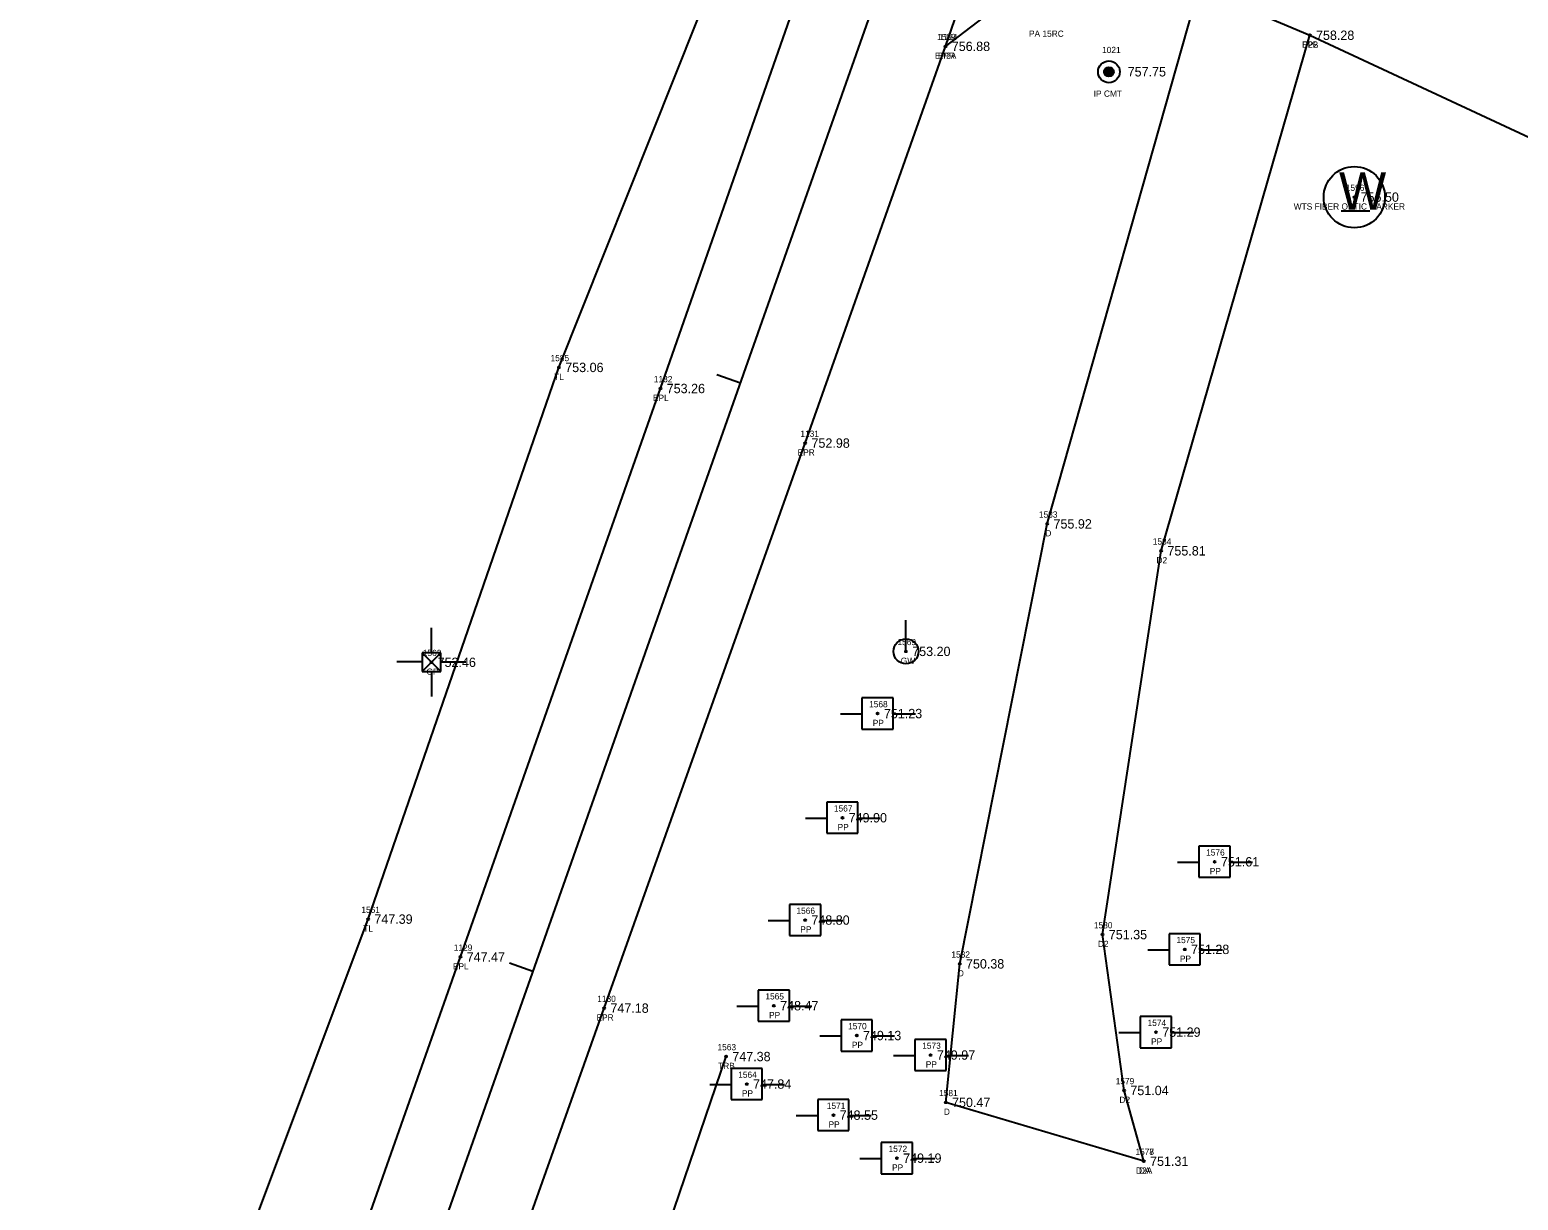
# Model space of a CAD drawing. Extents: x 1736563 to 1738032, y 1150548 to 1154248.
# Drawn here: x 1737559.1 to 1737797.6, y 1153273.7 to 1153461.3 of the extents above; entities that cross this region are included whole.
import ezdxf

# ---------------------------------------------------------------- set-up
doc = ezdxf.new("R2010")
doc.units = 0
for name, color, linetype in [('RD_EX_DR_Pipe_txCode', 7, 'Continuous'), ('RD_EX_Driveway', 7, 'Continuous'), ('RD_EX_Driveway_txCode', 7, 'Continuous'), ('RD_EX_DV_Prop_txCode', 7, 'Continuous'), ('RD_EX_DV_PropPin', 7, 'Continuous'), ('RD_EX_Road', 7, 'Continuous'), ('RD_EX_Road_txCode', 7, 'Continuous'), ('RD_EX_TX_Driveway_ELEV', 7, 'Continuous'), ('RD_EX_TX_DV_Prop_ELEV', 7, 'Continuous'), ('RD_EX_TX_Road_ELEV', 7, 'Continuous'), ('RD_EX_TX_UT_ELEV', 7, 'Continuous'), ('RD_EX_TX_VEG_ELEV', 7, 'Continuous'), ('RD_EX_UT', 7, 'Continuous'), ('RD_EX_UT_txCode', 7, 'Continuous'), ('RD_EX_VEG', 7, 'Continuous'), ('RD_EX_VEG_txCode', 7, 'Continuous'), ('RD_HC_Cl', 7, 'Continuous'), ('RD_HC_Data_Tic', 7, 'Continuous'), ('RD_HC_Survey_ELEV', 7, 'Continuous'), ('RD_SMD_Locator', 7, 'Continuous')]:
    doc.layers.add(name, color=color, linetype=linetype)

msp = doc.modelspace()

# ---------------------------------------------------------------- linework, layer by layer
at = {"layer": 'RD_EX_Driveway'}
for points in [[(1737737.65, 1153279.93), (1737705.92, 1153289.36), (1737708.15, 1153311.57), (1737722.18, 1153382.1), (1737746.44, 1153467.95)], [(1737737.65, 1153279.93), (1737734.49, 1153291.27), (1737731.04, 1153316.26), (1737740.43, 1153377.78), (1737764.24, 1153460.43)]]:
    msp.add_lwpolyline(points, dxfattribs=at)
at = {"layer": 'RD_EX_DV_PropPin'}
for p, q in [((1737731.32, 1153454.38), (1737731.32, 1153454.77)), ((1737731.36, 1153454.28), (1737731.36, 1153454.87)), ((1737731.4, 1153454.2), (1737731.4, 1153454.94)), ((1737731.43, 1153454.15), (1737731.43, 1153455)), ((1737731.47, 1153454.1), (1737731.47, 1153455.05)), ((1737731.5, 1153454.06), (1737731.5, 1153455.09)), ((1737731.54, 1153454.02), (1737731.54, 1153455.12)), ((1737731.57, 1153453.99), (1737731.57, 1153455.16)), ((1737731.61, 1153453.96), (1737731.61, 1153455.18)), ((1737731.64, 1153453.94), (1737731.64, 1153455.21)), ((1737731.68, 1153453.92), (1737731.68, 1153455.23)), ((1737731.71, 1153453.9), (1737731.71, 1153455.25)), ((1737731.75, 1153453.88), (1737731.75, 1153455.27)), ((1737731.78, 1153453.87), (1737731.78, 1153455.28)), ((1737731.82, 1153453.85), (1737731.82, 1153455.29)), ((1737731.85, 1153453.84), (1737731.85, 1153455.3)), ((1737731.89, 1153453.83), (1737731.89, 1153455.31)), ((1737731.92, 1153453.83), (1737731.92, 1153455.32)), ((1737731.96, 1153453.82), (1737731.96, 1153455.33)), ((1737731.99, 1153453.82), (1737731.99, 1153455.33)), ((1737732.03, 1153453.81), (1737732.03, 1153455.33)), ((1737732.06, 1153453.81), (1737732.06, 1153455.33)), ((1737732.1, 1153453.81), (1737732.1, 1153455.33)), ((1737732.13, 1153453.82), (1737732.13, 1153455.33)), ((1737732.17, 1153453.82), (1737732.17, 1153455.33)), ((1737732.2, 1153453.83), (1737732.2, 1153455.32)), ((1737732.24, 1153453.83), (1737732.24, 1153455.31)), ((1737732.27, 1153453.84), (1737732.27, 1153455.3)), ((1737732.31, 1153453.85), (1737732.31, 1153455.29)), ((1737732.34, 1153453.87), (1737732.34, 1153455.28)), ((1737732.38, 1153453.88), (1737732.38, 1153455.27)), ((1737732.41, 1153453.9), (1737732.41, 1153455.25)), ((1737732.45, 1153453.92), (1737732.45, 1153455.23)), ((1737732.48, 1153453.94), (1737732.48, 1153455.21)), ((1737732.52, 1153453.96), (1737732.52, 1153455.18)), ((1737732.55, 1153453.99), (1737732.55, 1153455.16)), ((1737732.59, 1153454.02), (1737732.59, 1153455.12)), ((1737732.62, 1153454.06), (1737732.62, 1153455.09)), ((1737732.66, 1153454.1), (1737732.66, 1153455.05)), ((1737732.69, 1153454.15), (1737732.69, 1153455)), ((1737732.73, 1153454.2), (1737732.73, 1153454.94)), ((1737732.76, 1153454.28), (1737732.76, 1153454.87)), ((1737732.8, 1153454.38), (1737732.8, 1153454.77))]:
    msp.add_line(p, q, dxfattribs=at)
for radius in [1.75, 0.761]:
    msp.add_circle((1737732.06, 1153454.57), radius, dxfattribs=at)
at = {"layer": 'RD_EX_Road'}
for points in [[(1737496.36, 1152940.55), (1737529.37, 1153032.75), (1737537.93, 1153057.4), (1737549.32, 1153089.17), (1737563.01, 1153127.73), (1737595.49, 1153219.95), (1737628.15, 1153312.67), (1737660.2, 1153403.8), (1737692.32, 1153495.67), (1737724.61, 1153587.75), (1737756.73, 1153679.29), (1737770.32, 1153718.5), (1737778.01, 1153740.46), (1737788.96, 1153772.48), (1737822.56, 1153867.79), (1737856.1, 1153962.19), (1737875.63, 1154016.18), (1737880.55, 1154030.08), (1737889.82, 1154055.89), (1737923.73, 1154151.97)], [(1737552.4, 1153024.11), (1737569.73, 1153074.37), (1737580.02, 1153102.83), (1737585.88, 1153119.72), (1737600.61, 1153161.43), (1737609.53, 1153186.52), (1737618.32, 1153211.94), (1737651.18, 1153304.47), (1737683.4, 1153395.05), (1737705.88, 1153458.65), (1737715.8, 1153487.43), (1737725.08, 1153513.79), (1737730.46, 1153529.07), (1737746.67, 1153575.11), (1737767.23, 1153635.63), (1737779.62, 1153670.7)], [(1737705.88, 1153458.65), (1737721.44, 1153470.54), (1737736.82, 1153470.58), (1737746.44, 1153467.95), (1737764.24, 1153460.43), (1737799.45, 1153444.03)]]:
    msp.add_lwpolyline(points, dxfattribs=at)
at = {"layer": 'RD_EX_UT'}
for p, q in [((1737769.25, 1153432.27), (1737773.88, 1153432.27)), ((1737699.54, 1153361.66), (1737699.54, 1153366.66)), ((1737623.49, 1153361.41), (1737623.49, 1153365.41)), ((1737624.99, 1153361.41), (1737621.99, 1153358.41)), ((1737621.99, 1153361.41), (1737624.99, 1153358.41)), ((1737624.99, 1153361.41), (1737621.99, 1153361.41)), ((1737621.99, 1153361.41), (1737621.99, 1153358.41)), ((1737624.99, 1153358.41), (1737624.99, 1153361.41)), ((1737621.96, 1153359.96), (1737617.96, 1153359.96)), ((1737625, 1153359.97), (1737629.02, 1153359.97)), ((1737621.99, 1153358.41), (1737624.99, 1153358.41)), ((1737623.49, 1153358.41), (1737623.49, 1153354.41)), ((1737697.49, 1153354.2), (1737692.49, 1153354.2)), ((1737692.49, 1153354.2), (1737692.49, 1153349.2)), ((1737697.49, 1153349.2), (1737697.49, 1153354.2)), ((1737689.06, 1153351.63), (1737692.53, 1153351.63)), ((1737697.42, 1153351.63), (1737701.06, 1153351.63)), ((1737692.49, 1153349.2), (1737697.49, 1153349.2)), ((1737691.85, 1153337.5), (1737686.85, 1153337.5)), ((1737686.85, 1153337.5), (1737686.85, 1153332.5)), ((1737691.85, 1153332.5), (1737691.85, 1153337.5)), ((1737683.42, 1153334.94), (1737686.89, 1153334.94)), ((1737691.78, 1153334.94), (1737695.42, 1153334.94)), ((1737686.85, 1153332.5), (1737691.85, 1153332.5)), ((1737751.49, 1153330.44), (1737746.49, 1153330.44)), ((1737746.49, 1153330.44), (1737746.49, 1153325.44)), ((1737751.49, 1153325.44), (1737751.49, 1153330.44)), ((1737743.06, 1153327.88), (1737746.53, 1153327.88)), ((1737751.42, 1153327.88), (1737755.06, 1153327.88)), ((1737746.49, 1153325.44), (1737751.49, 1153325.44)), ((1737685.87, 1153321.1), (1737680.87, 1153321.1)), ((1737680.87, 1153321.1), (1737680.87, 1153316.1)), ((1737685.87, 1153316.1), (1737685.87, 1153321.1)), ((1737677.44, 1153318.54), (1737680.91, 1153318.54)), ((1737685.8, 1153318.54), (1737689.44, 1153318.54)), ((1737680.87, 1153316.1), (1737685.87, 1153316.1)), ((1737746.7, 1153316.4), (1737741.7, 1153316.4)), ((1737741.7, 1153316.4), (1737741.7, 1153311.4)), ((1737746.7, 1153311.4), (1737746.7, 1153316.4)), ((1737738.27, 1153313.84), (1737741.74, 1153313.84)), ((1737746.63, 1153313.84), (1737750.27, 1153313.84)), ((1737741.7, 1153311.4), (1737746.7, 1153311.4)), ((1737680.87, 1153307.37), (1737675.87, 1153307.37)), ((1737675.87, 1153307.37), (1737675.87, 1153302.37)), ((1737680.87, 1153302.37), (1737680.87, 1153307.37)), ((1737672.44, 1153304.81), (1737675.91, 1153304.81)), ((1737680.8, 1153304.81), (1737684.44, 1153304.81)), ((1737675.87, 1153302.37), (1737680.87, 1153302.37)), ((1737694.14, 1153302.59), (1737689.14, 1153302.59)), ((1737689.14, 1153302.59), (1737689.14, 1153297.59)), ((1737694.14, 1153297.59), (1737694.14, 1153302.59)), ((1737742.09, 1153303.12), (1737737.09, 1153303.12)), ((1737737.09, 1153303.12), (1737737.09, 1153298.12)), ((1737742.09, 1153298.12), (1737742.09, 1153303.12)), ((1737685.71, 1153300.03), (1737689.18, 1153300.03)), ((1737694.07, 1153300.03), (1737697.71, 1153300.03)), ((1737705.98, 1153299.46), (1737700.98, 1153299.46)), ((1737700.98, 1153299.46), (1737700.98, 1153294.46)), ((1737705.98, 1153294.46), (1737705.98, 1153299.46)), ((1737733.66, 1153300.56), (1737737.13, 1153300.56)), ((1737742.02, 1153300.56), (1737745.66, 1153300.56)), ((1737689.14, 1153297.59), (1737694.14, 1153297.59)), ((1737697.55, 1153296.9), (1737701.02, 1153296.9)), ((1737705.91, 1153296.9), (1737709.55, 1153296.9)), ((1737737.09, 1153298.12), (1737742.09, 1153298.12)), ((1737676.52, 1153294.81), (1737671.52, 1153294.81)), ((1737671.52, 1153294.81), (1737671.52, 1153289.81)), ((1737676.52, 1153289.81), (1737676.52, 1153294.81)), ((1737700.98, 1153294.46), (1737705.98, 1153294.46)), ((1737668.09, 1153292.24), (1737671.56, 1153292.24)), ((1737676.45, 1153292.24), (1737680.09, 1153292.24)), ((1737671.52, 1153289.81), (1737676.52, 1153289.81)), ((1737690.4, 1153289.83), (1737685.4, 1153289.83)), ((1737685.4, 1153289.83), (1737685.4, 1153284.83)), ((1737690.4, 1153284.83), (1737690.4, 1153289.83)), ((1737681.97, 1153287.27), (1737685.44, 1153287.27)), ((1737690.33, 1153287.27), (1737693.97, 1153287.27)), ((1737685.4, 1153284.83), (1737690.4, 1153284.83)), ((1737700.58, 1153282.92), (1737695.58, 1153282.92)), ((1737695.58, 1153282.92), (1737695.58, 1153277.92)), ((1737700.58, 1153277.92), (1737700.58, 1153282.92)), ((1737692.15, 1153280.36), (1737695.62, 1153280.36)), ((1737700.51, 1153280.36), (1737704.15, 1153280.36)), ((1737695.58, 1153277.92), (1737700.58, 1153277.92))]:
    msp.add_line(p, q, dxfattribs=at)
for centre, radius in [((1737771.38, 1153434.47), 4.91), ((1737699.54, 1153361.66), 2)]:
    msp.add_circle(centre, radius, dxfattribs=at)
at = {"layer": 'RD_EX_VEG'}
for points in [[(1737451.48, 1152925.19), (1737471.83, 1152967.5), (1737483.5, 1153062.03), (1737523.53, 1153143.47), (1737578.4, 1153225.34), (1737613.35, 1153318.74), (1737643.94, 1153407.18), (1737681, 1153500.22), (1737713.81, 1153596.51), (1737742.54, 1153686.46), (1737776.37, 1153777.24), (1737812.9, 1153871.37), (1737847.32, 1153964.45), (1737872.45, 1154065.49)], [(1737529.35, 1152765.74), (1737562.26, 1152829.1), (1737577.12, 1153014.16), (1737637.48, 1153199.14), (1737670.71, 1153296.71)]]:
    msp.add_lwpolyline(points, dxfattribs=at)
at = {"layer": 'RD_HC_Cl'}
msp.add_line((1736879.96, 1151154.46), (1737935.1, 1154148.31), dxfattribs=at)
at = {"layer": 'RD_HC_Data_Tic'}
for p, q in [((1737673.01, 1153404.64), (1737669.23, 1153405.97)), ((1737639.77, 1153310.33), (1737636, 1153311.66))]:
    msp.add_line(p, q, dxfattribs=at)
at = {"layer": 'RD_SMD_Locator'}
for centre in [(1737764.24, 1153460.43), (1737764.24, 1153460.43), (1737705.88, 1153458.65), (1737705.88, 1153458.65), (1737732.06, 1153454.57), (1737771.38, 1153434.47), (1737643.94, 1153407.18), (1737660.2, 1153403.8), (1737683.4, 1153395.05), (1737722.18, 1153382.1), (1737740.43, 1153377.78), (1737699.54, 1153361.66), (1737623.49, 1153359.91), (1737695, 1153351.69), (1737689.36, 1153334.99), (1737749, 1153327.93), (1737613.35, 1153318.74), (1737683.38, 1153318.59), (1737731.04, 1153316.26), (1737744.21, 1153313.89), (1737628.15, 1153312.67), (1737708.15, 1153311.57), (1737651.18, 1153304.47), (1737678.38, 1153304.86), (1737691.65, 1153300.08), (1737739.6, 1153300.62), (1737670.71, 1153296.71), (1737703.49, 1153296.95), (1737674.03, 1153292.3), (1737734.49, 1153291.27), (1737687.91, 1153287.32), (1737705.92, 1153289.36), (1737698.09, 1153280.42), (1737737.65, 1153279.93), (1737737.65, 1153279.93)]:
    msp.add_circle(centre, 0.15, dxfattribs=at)

# ---------------------------------------------------------------- texts
at = {"layer": 'RD_EX_DR_Pipe_txCode'}
msp.add_text('PA 15RC', height=1, dxfattribs=at).set_placement((1737719.25, 1153460.18))
at = {"layer": 'RD_EX_Driveway_txCode'}
for s, p in [('D2B', (1737763.01, 1153458.43)), ('1583', (1737720.84, 1153383.1)), ('D', (1737721.87, 1153380.1)), ('1584', (1737739.08, 1153378.78)), ('D2', (1737739.67, 1153375.78)), ('1580', (1737729.65, 1153317.26)), ('1582', (1737706.81, 1153312.57)), ('D2', (1737730.28, 1153314.26)), ('D', (1737707.85, 1153309.57)), ('1579', (1737733.14, 1153292.27)), ('1581', (1737704.85, 1153290.36)), ('D2', (1737733.74, 1153289.27)), ('D', (1737705.61, 1153287.36)), ('1578', (1737736.3, 1153280.93)), ('1577', (1737736.3, 1153280.93)), ('D2A', (1737736.4, 1153277.93)), ('DA', (1737736.85, 1153277.93))]:
    msp.add_text(s, height=1, dxfattribs=at).set_placement(p)
at = {"layer": 'RD_EX_DV_Prop_txCode'}
for s, p in [('1021', (1737730.96, 1153457.57)), ('IP CMT', (1737729.62, 1153450.57))]:
    msp.add_text(s, height=1, dxfattribs=at).set_placement(p)
at = {"layer": 'RD_EX_Road_txCode'}
for s, p in [('1589', (1737704.53, 1153459.65)), ('1134', (1737704.82, 1153459.65)), ('EP2', (1737763.03, 1153458.43)), ('EP2A', (1737704.19, 1153456.65)), ('EPR', (1737704.65, 1153456.65)), ('1132', (1737659.14, 1153404.8)), ('EPL', (1737658.99, 1153401.8)), ('1131', (1737682.62, 1153396.05)), ('EPR', (1737682.17, 1153393.05)), ('1129', (1737627.08, 1153313.67)), ('EPL', (1737626.94, 1153310.67)), ('1130', (1737650.07, 1153305.47)), ('EPR', (1737649.95, 1153302.47))]:
    msp.add_text(s, height=1, dxfattribs=at).set_placement(p)
at = {"layer": 'RD_EX_TX_Driveway_ELEV'}
for s, p in [('758.28', (1737765.24, 1153459.68)), ('755.92', (1737723.18, 1153381.35)), ('755.81', (1737741.43, 1153377.03)), ('751.35', (1737732.04, 1153315.51)), ('750.38', (1737709.15, 1153310.82)), ('751.04', (1737735.49, 1153290.52)), ('750.47', (1737706.92, 1153288.61)), ('751.31', (1737738.65, 1153279.18)), ('751.31', (1737738.65, 1153279.18))]:
    msp.add_text(s, height=1.5, dxfattribs=at).set_placement(p)
at = {"layer": 'RD_EX_TX_DV_Prop_ELEV'}
msp.add_text('757.75', height=1.5, dxfattribs=at).set_placement((1737735.06, 1153453.82))
at = {"layer": 'RD_EX_TX_Road_ELEV'}
for s, p in [('756.88', (1737706.88, 1153457.9)), ('756.88', (1737706.88, 1153457.9)), ('758.28', (1737765.24, 1153459.68)), ('753.26', (1737661.2, 1153403.05)), ('752.98', (1737684.4, 1153394.3)), ('747.47', (1737629.15, 1153311.92)), ('747.18', (1737652.18, 1153303.72))]:
    msp.add_text(s, height=1.5, dxfattribs=at).set_placement(p)
at = {"layer": 'RD_EX_TX_UT_ELEV'}
for s, p in [('756.50', (1737772.38, 1153433.73)), ('753.20', (1737700.54, 1153360.91)), ('752.46', (1737624.49, 1153359.16))]:
    msp.add_text(s, height=1.5, dxfattribs=at).set_placement(p)
at = {"layer": 'RD_EX_TX_VEG_ELEV'}
for s, p in [('753.06', (1737644.94, 1153406.43)), ('747.39', (1737614.35, 1153317.99)), ('747.38', (1737671.71, 1153295.96))]:
    msp.add_text(s, height=1.5, dxfattribs=at).set_placement(p)
at = {"layer": 'RD_EX_UT'}
msp.add_text('W', height=6, dxfattribs=at).set_placement((1737768.92, 1153432.47))
at = {"layer": 'RD_EX_UT_txCode'}
for s, p in [('1596', (1737770.01, 1153435.48)), ('WTS FIBER OPTIC MARKER', (1737761.67, 1153432.48)), ('1569', (1737698.17, 1153362.66)), ('1562', (1737622.12, 1153360.91)), ('GP', (1737622.71, 1153357.91)), ('GW', (1737698.7, 1153359.66)), ('1568', (1737693.63, 1153352.69)), ('PP', (1737694.22, 1153349.69)), ('1567', (1737687.99, 1153335.99)), ('PP', (1737688.58, 1153332.99)), ('1576', (1737747.63, 1153328.93)), ('PP', (1737748.22, 1153325.93)), ('1566', (1737681.99, 1153319.59)), ('PP', (1737682.6, 1153316.59)), ('1575', (1737742.87, 1153314.89)), ('PP', (1737743.43, 1153311.89)), ('1565', (1737677.01, 1153305.86)), ('PP', (1737677.6, 1153302.86)), ('1570', (1737690.26, 1153301.08)), ('1574', (1737738.25, 1153301.62)), ('PP', (1737738.82, 1153298.62)), ('PP', (1737690.87, 1153298.08)), ('1573', (1737702.14, 1153297.95)), ('PP', (1737702.71, 1153294.95)), ('1564', (1737672.66, 1153293.3)), ('PP', (1737673.25, 1153290.3)), ('1571', (1737686.85, 1153288.32)), ('PP', (1737687.13, 1153285.32)), ('1572', (1737696.75, 1153281.42)), ('PP', (1737697.31, 1153278.42))]:
    msp.add_text(s, height=1, dxfattribs=at).set_placement(p)
at = {"layer": 'RD_EX_VEG_txCode'}
for s, p in [('1585', (1737642.59, 1153408.18)), ('TL', (1737643.16, 1153405.18)), ('1561', (1737612.27, 1153319.74)), ('TL', (1737612.58, 1153316.74)), ('1563', (1737669.34, 1153297.71)), ('TRB', (1737669.44, 1153294.71))]:
    msp.add_text(s, height=1, dxfattribs=at).set_placement(p)
at = {"layer": 'RD_HC_Survey_ELEV'}
for s, p in [('751.23', (1737696, 1153350.94)), ('749.90', (1737690.36, 1153334.24)), ('751.61', (1737750, 1153327.18)), ('748.80', (1737684.38, 1153317.84)), ('751.28', (1737745.21, 1153313.14)), ('748.47', (1737679.38, 1153304.11)), ('749.13', (1737692.65, 1153299.33)), ('751.29', (1737740.6, 1153299.87)), ('749.97', (1737704.49, 1153296.2)), ('747.84', (1737675.03, 1153291.55)), ('748.55', (1737688.91, 1153286.57)), ('749.19', (1737699.09, 1153279.67))]:
    msp.add_text(s, height=1.5, dxfattribs=at).set_placement(p)

doc.saveas('drawing.dxf')
